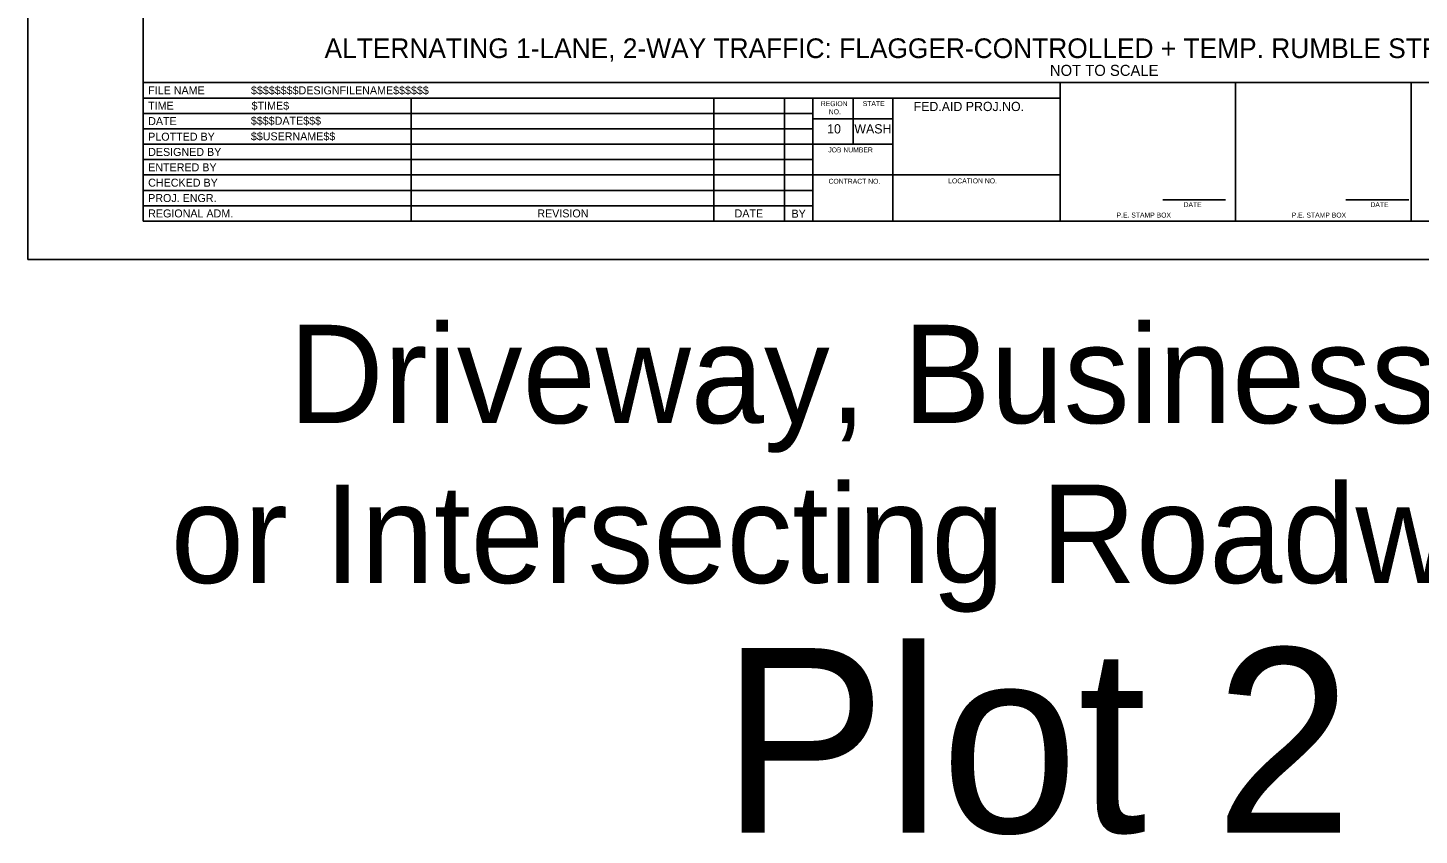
# Model space of a CAD drawing. Extents: x 99999.1 to 100095.7, y 99995 to 100010.7.
# Drawn here: x 100019.06 to 100030.38, y 99995.01 to 100001.57 of the extents above; entities that cross this region are included whole.
import ezdxf

# ---------------------------------------------------------------- set-up
doc = ezdxf.new("R2010")
doc.units = 0
for name, color, linetype in [('SH_DE_DetailHeading1Text', 7, 'Continuous'), ('SH_GI_PlotLimits', 7, 'Continuous'), ('SH_GI_SheetBorder', 7, 'Continuous'), ('SH_GI_SheetLocationText', 7, 'Continuous'), ('SH_GI_SheetTextInCells', 7, 'Continuous'), ('SH_GI_TitleBlockText', 7, 'Continuous')]:
    doc.layers.add(name, color=color, linetype=linetype)

msp = doc.modelspace()

# ---------------------------------------------------------------- linework, layer by layer
at = {"layer": 'SH_GI_PlotLimits'}
msp.add_lwpolyline([(100019.062, 99999.687), (100036.062, 99999.687), (100036.062, 100010.687), (100019.062, 100010.687)], close=True, dxfattribs=at)
at = {"layer": 'SH_GI_SheetBorder'}
for p, q in [((100020, 100010.375), (100020, 100000)), ((100020, 100001.126), (100035.75, 100001.126)), ((100027.457, 100000), (100027.457, 100001.126)), ((100028.883, 100000), (100028.883, 100001.126)), ((100030.309, 100001.126), (100030.309, 100000)), ((100020, 100001.001), (100027.457, 100001.001)), ((100022.179, 100001.001), (100022.179, 100000)), ((100024.641, 100001.001), (100024.641, 100000)), ((100025.216, 100001.001), (100025.216, 100000)), ((100025.445, 100001.001), (100025.445, 100000)), ((100025.772, 100000.625), (100025.772, 100001.001)), ((100026.096, 100000), (100026.096, 100001.001)), ((100020, 100000.876), (100022.182, 100000.876)), ((100022.182, 100000.876), (100025.447, 100000.876)), ((100026.096, 100000.831), (100025.447, 100000.831)), ((100020, 100000.751), (100022.182, 100000.751)), ((100022.182, 100000.751), (100025.447, 100000.751)), ((100020, 100000.625), (100025.447, 100000.625)), ((100026.096, 100000.625), (100025.447, 100000.625)), ((100020, 100000.5), (100025.447, 100000.5)), ((100020, 100000.375), (100025.447, 100000.375)), ((100027.457, 100000.375), (100025.447, 100000.375)), ((100020, 100000.25), (100025.447, 100000.25)), ((100020, 100000.125), (100025.447, 100000.125)), ((100028.29, 100000.173), (100028.802, 100000.173)), ((100029.78, 100000.173), (100030.291, 100000.173)), ((100020, 100000), (100035.75, 100000))]:
    msp.add_line(p, q, dxfattribs=at)

# ---------------------------------------------------------------- texts
at = {"layer": 'SH_DE_DetailHeading1Text'}
for s, height, p in [('ALTERNATING 1-LANE, 2-WAY TRAFFIC: FLAGGER-CONTROLLED + TEMP. RUMBLE STRIPS (45+ MPH HIGHWAYS)', 0.16, (100021.475, 100001.326)), ('NOT TO SCALE', 0.09, (100027.373, 100001.181))]:
    msp.add_text(s, height=height, rotation=360, dxfattribs=at).set_placement(p)
at = {"layer": 'SH_GI_SheetLocationText'}
for s, height, p in [('Driveway, Business Access,', 0.8, (100021.184, 99998.357)), ('or Intersecting Roadway Details', 0.8, (100020.225, 99997.057)), ('Plot 2', 1.5, (100024.702, 99995.027))]:
    msp.add_text(s, height=height, dxfattribs=at).set_placement(p)
at = {"layer": 'SH_GI_SheetTextInCells'}
for s, height, p in [('FILE NAME', 0.0651, (100020.041, 100001.031)), ('TIME', 0.0651, (100020.041, 100000.906)), ('REGION', 0.04, (100025.51, 100000.935)), ('NO.', 0.04, (100025.575, 100000.869)), ('STATE', 0.04, (100025.851, 100000.936)), ('FED.AID PROJ.NO.', 0.07506, (100026.265, 100000.895)), ('DATE', 0.0651, (100020.041, 100000.781)), ('10', 0.0751, (100025.562, 100000.713)), ('WASH', 0.0751, (100025.783, 100000.713)), ('PLOTTED BY', 0.0651, (100020.041, 100000.654)), ('DESIGNED BY', 0.06505, (100020.041, 100000.53)), ('JOB NUMBER', 0.04, (100025.571, 100000.559)), ('ENTERED BY', 0.0651, (100020.041, 100000.405)), ('CHECKED BY', 0.0651, (100020.041, 100000.28)), ('CONTRACT NO.', 0.04003, (100025.573, 100000.304)), ('LOCATION NO.', 0.04003, (100026.546, 100000.307)), ('PROJ. ENGR.', 0.06505, (100020.041, 100000.155)), ('REGIONAL ADM.', 0.06505, (100020.041, 100000.03)), ('REVISION', 0.0651, (100023.205, 100000.03)), ('DATE', 0.04, (100028.46, 100000.114)), ('DATE', 0.04, (100029.979, 100000.114)), ('DATE', 0.0651, (100024.809, 100000.03)), ('BY', 0.0651, (100025.272, 100000.028)), ('P.E. STAMP BOX', 0.04003, (100027.915, 100000.029)), ('P.E. STAMP BOX', 0.04003, (100029.339, 100000.029))]:
    msp.add_text(s, height=height, dxfattribs=at).set_placement(p)
at = {"layer": 'SH_GI_TitleBlockText'}
for s, height, p in [('$$$$$$$$DESIGNFILENAME$$$$$$', 0.06505, (100020.877, 100001.031)), ('$TIME$', 0.0651, (100020.882, 100000.906)), ('$$$$DATE$$$', 0.06505, (100020.876, 100000.784)), ('$$USERNAME$$', 0.06505, (100020.876, 100000.657))]:
    msp.add_text(s, height=height, dxfattribs=at).set_placement(p)

doc.saveas('drawing.dxf')
